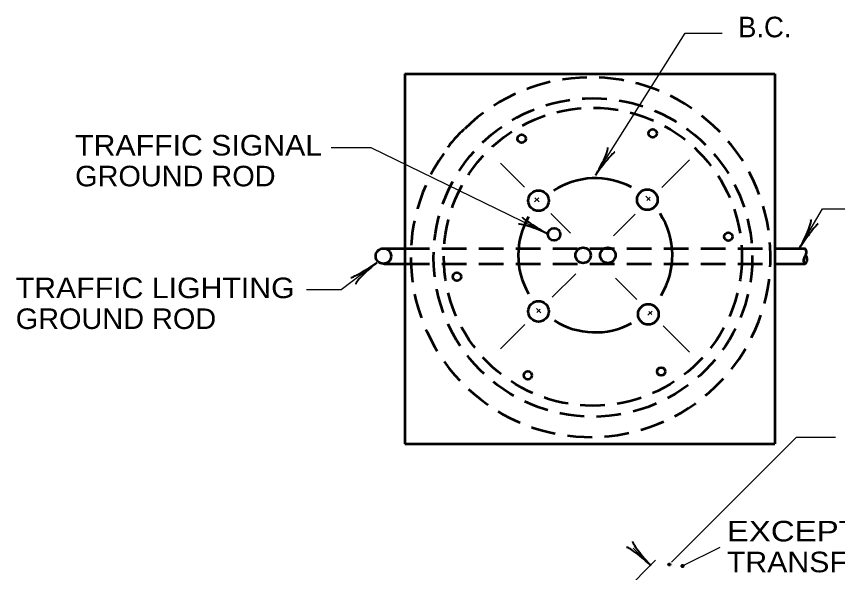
# Model space of a CAD drawing. Extents: x -560 to 120, y 26 to 466.
# Drawn here: x -191 to -111.1, y 176.3 to 230.4 of the extents above; entities that cross this region are included whole.
import ezdxf

# ---------------------------------------------------------------- set-up
doc = ezdxf.new("R2010")
doc.units = 0
doc.header["$LTSCALE"] = 0.8
doc.linetypes.add('MEDIUM_DASHED', pattern=[4.5, 3, -1.5])
doc.layers.add('1', color=7, linetype='Continuous', lineweight=53)

msp = doc.modelspace()

# ---------------------------------------------------------------- linework, layer by layer
at = {"layer": '1'}
for p, q in [((-153.2122, 224.8415), (-153.2122, 188.8415)), ((-153.2122, 224.8415), (-117.2122, 224.8415)), ((-117.2122, 224.8415), (-117.2122, 188.8415)), ((-155.2229, 207.8417), (-153.2229, 207.8417)), ((-117.2902, 207.8368), (-114.2902, 207.8368)), ((-155.2182, 206.3463), (-153.2182, 206.3463)), ((-117.2807, 206.3369), (-114.2807, 206.3369)), ((-153.2122, 188.8415), (-117.2122, 188.8415))]:
    msp.add_line(p, q, dxfattribs=at)
at = {"layer": '1', "lineweight": 35}
for p, q in [((-143.913, 216.1422), (-141.5695, 213.7987)), ((-128.2188, 213.7597), (-125.5251, 216.4535)), ((-140.6026, 212.3689), (-140.1899, 212.7814)), ((-140.5571, 212.7863), (-140.1446, 212.3738)), ((-129.7578, 212.9363), (-129.3453, 212.5238)), ((-129.6892, 212.5143), (-129.3612, 212.8424)), ((-139.0197, 211.249), (-137.096, 209.3252)), ((-132.9173, 209.0613), (-130.8061, 211.1724)), ((-138.8679, 203.1107), (-136.5922, 205.3864)), ((-132.7087, 204.9379), (-130.6579, 202.8872)), ((-140.4071, 201.9871), (-139.9946, 201.5746)), ((-140.3807, 201.5979), (-140.0432, 201.9354)), ((-129.5783, 201.3447), (-129.1657, 201.7572)), ((-129.4955, 201.7248), (-129.1956, 201.4248)), ((-143.9098, 198.0687), (-141.5302, 200.4483)), ((-128.0707, 200.2999), (-125.5282, 197.7575))]:
    msp.add_line(p, q, dxfattribs=at)
at = {"layer": '1', "linetype": 'MEDIUM_DASHED'}
for p, q in [((-153.2122, 207.8415), (-117.2122, 207.8415)), ((-153.2122, 206.3415), (-117.2122, 206.3415))]:
    msp.add_line(p, q, dxfattribs=at)
at = {"layer": '1', "lineweight": 25}
for p, q in [((-130.9901, 178.6873), (-129.3106, 177.0078)), ((-126.2118, 176.9673), (-122.5358, 178.7678)), ((-132.3537, 173.9647), (-128.8183, 177.5002))]:
    msp.add_line(p, q, dxfattribs=at)
for points in [[(-134.6512, 214.9948), (-125.9471, 228.7835), (-122.3507, 228.7835)], [(-139.376, 209.2952), (-156.4752, 217.6197), (-160.3757, 217.6197)], [(-114.7771, 207.9452), (-112.6022, 211.695), (-108.9266, 211.695)], [(-155.9502, 206.4452), (-159.4001, 203.8204), (-162.7757, 203.8204)], [(-127.2779, 177.333), (-115.124, 189.487), (-111.3163, 189.4699)]]:
    msp.add_lwpolyline(points, dxfattribs=at)
at = {"layer": '1', "linetype": 'MEDIUM_DASHED'}
for centre, radius in [((-134.9231, 206.9665), 15.5), ((-134.9231, 207.0415), 14.5)]:
    msp.add_circle(centre, radius, dxfattribs=at)
at = {"layer": '1'}
for centre, radius in [((-141.8508, 218.5197), 0.4), ((-129.1014, 219.0447), 0.4), ((-140.2136, 212.4957), 1), ((-129.6294, 212.5911), 1), ((-138.701, 209.2202), 0.6), ((-121.7518, 208.9952), 0.4), ((-155.2978, 207.101), 0.75), ((-135.8738, 207.176), 0.75), ((-133.4738, 207.176), 0.75), ((-148.1506, 205.0953), 0.4), ((-140.2136, 201.7209), 1), ((-129.5341, 201.4348), 1), ((-141.2509, 195.4957), 0.4), ((-128.2765, 195.8707), 0.4), ((-127.4911, 177.0944), 0.0786), ((-126.2026, 176.9427), 0.0786)]:
    msp.add_circle(centre, radius, dxfattribs=at)
at = {"layer": '1', "linetype": 'MEDIUM_DASHED'}
for centre, radius, start, end in [((-135.1387, 206.993), 17.5, 144.72797, 134.59975), ((-140.5228, 211.5649), 10.4827, 131.18966, 148.13779)]:
    msp.add_arc(centre, radius, start, end, dxfattribs=at)
at = {"layer": '1'}
for start, end in [(61.93145, 122.73056), (150.00307, 209.99693), (328.65081, 32.73064), (237.9532, 298.03362)]:
    msp.add_arc((-134.6887, 207.1807), 7.5, start, end, dxfattribs=at)
at = {"layer": '1', "lineweight": 40}
for centre, major_axis, ratio, start_param, end_param in [((-134.3023, 216.0651), (-0.8212, -1.5934), 0.122415, 0.8963533, 3.1415927), ((-133.8741, 215.8294), (1.0861, 1.3915), 0.07063, 6.2823074, 8.5597026), ((-140.2908, 209.9759), (1.5024, -0.9268), 0.07063, 3.1407148, 5.41811), ((-140.4781, 209.5244), (1.6739, -0.6412), 0.122415, 0.8963533, 3.1415927), ((-114.4686, 209.0277), (-0.7608, -1.623), 0.122415, 0.8963533, 3.1415927), ((-114.0319, 208.8083), (-1.0332, -1.4313), 0.07063, 3.1407148, 5.41811), ((-156.9701, 205.9352), (-1.5042, -0.9238), 0.07063, 6.2823074, 8.5597026), ((-156.6514, 205.5646), (1.3266, 1.2055), 0.122415, 0.8963533, 3.1415927), ((-129.9533, 177.9498), (1.1178, -1.3662), 0.07063, 3.1407148, 5.41811), ((-129.9533, 177.9498), (1.1178, -1.3662), 0.07063, 3.1407148, 5.41811), ((-130.2776, 177.5841), (1.3731, -1.1523), 0.122415, 0.8963533, 3.1415927), ((-130.2776, 177.5841), (1.3731, -1.1523), 0.122415, 0.8963533, 3.1415927)]:
    msp.add_ellipse(centre, major_axis=major_axis, ratio=ratio, start_param=start_param, end_param=end_param, dxfattribs=at)
at = {"layer": '1'}
for centre, major_axis, ratio, start_param, end_param in [((-114.7231, 207.4027), (0.433, 0.4342), 0.896364, 4.6732248, 6.2831853), ((-113.8654, 206.7839), (-0.4342, -0.433), 0.84388, 4.7124091, 6.3349528), ((-114.6528, 206.7417), (0.433, 0.4342), 0.896364, 4.6732248, 6.2831853)]:
    msp.add_ellipse(centre, major_axis=major_axis, ratio=ratio, start_param=start_param, end_param=end_param, dxfattribs=at)
msp.add_spline([(-126.2212, 176.9858), (-126.2118, 176.9578), (-126.2118, 176.9389), (-126.2025, 176.9202), (-126.1743, 176.9202), (-126.165, 176.9202), (-126.1743, 176.9483), (-126.2025, 176.9483), (-126.2307, 176.9483), (-126.24, 176.9108), (-126.2025, 176.9858), (-126.1931, 176.9578), (-126.1931, 176.9108), (-126.2212, 176.8921), (-126.2212, 176.9578), (-126.2025, 176.9578), (-126.165, 176.9483), (-126.1931, 176.9858), (-126.2307, 176.9578), (-126.1931, 176.9014), (-126.1931, 176.9765), (-126.2025, 176.9671), (-126.2118, 176.9483), (-126.2118, 176.9952), (-126.1931, 176.9671), (-126.2212, 176.9671), (-126.2307, 176.9578), (-126.2025, 176.9296)], degree=3, dxfattribs=at)

# ---------------------------------------------------------------- texts
msp.add_text('B.C.', height=2, dxfattribs=at).set_placement((-120.8018, 228.3929))
for s, width, p in [('TRAFFIC SIGNAL', 1.1, (-185.288, 216.8883)), ('GROUND ROD', 1.05, (-185.288, 213.8883)), ('TRAFFIC LIGHTING', 1.1, (-191.0652, 203.0083)), ('GROUND ROD', 1.05, (-191.0652, 200.0083)), ('EXCEPT USE 3" WHEN USING', 1.2, (-121.8897, 179.3371)), ('TRANSF. BASES', 1.1, (-121.8897, 176.3371))]:
    msp.add_text(s, height=2, dxfattribs=dict(at, width=width)).set_placement(p)

doc.saveas('drawing.dxf')
